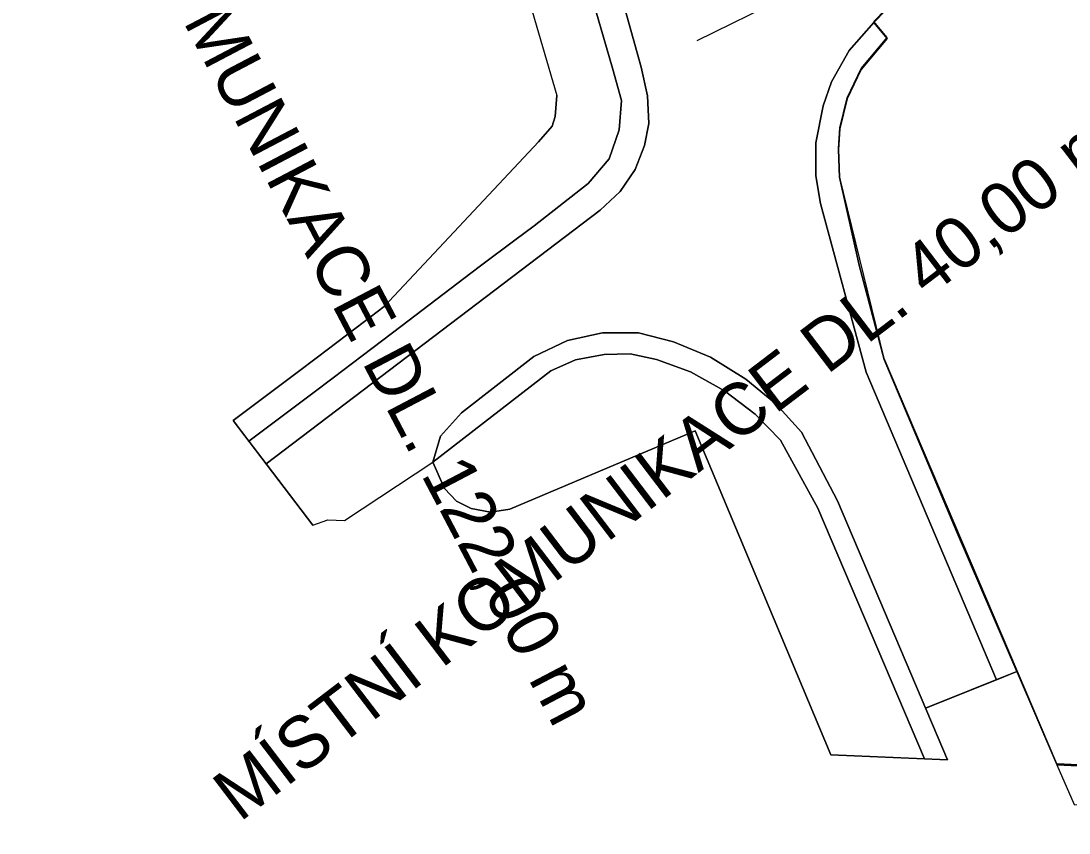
# Model space of a CAD drawing. Extents: x -606444 to -604546, y -1158114 to -1156869.
# Drawn here: x -605208.5 to -605127.5, y -1157433.2 to -1157370.5 of the extents above; entities that cross this region are included whole.
import ezdxf

# ---------------------------------------------------------------- set-up
doc = ezdxf.new("R2010")
doc.units = 0
for name, color, linetype in [('B_CHOD', 7, 'Continuous'), ('B_VOZ', 7, 'Continuous'), ('B_ZELEN', 7, 'Continuous'), ('NS_VB', 7, 'Continuous'), ('NS_VB_POP', 7, 'Continuous'), ('OSAPOP', 7, 'Continuous')]:
    doc.layers.add(name, color=color, linetype=linetype)

msp = doc.modelspace()

# ---------------------------------------------------------------- linework, layer by layer
at = {"layer": 'B_CHOD'}
for p, q in [((-605142.56, -1157370.59), (-605144.46, -1157372.75)), ((-605141.53, -1157371.81), (-605142.56, -1157370.59)), ((-605143.54, -1157374.22), (-605141.53, -1157371.81)), ((-605144.46, -1157372.75), (-605145.82, -1157375.16)), ((-605144.61, -1157376.48), (-605143.54, -1157374.22)), ((-605145.82, -1157375.16), (-605146.48, -1157377.03)), ((-605145.18, -1157378.79), (-605144.61, -1157376.48)), ((-605146.48, -1157377.03), (-605147.04, -1157379.89)), ((-605145.29, -1157380.41), (-605145.18, -1157378.79)), ((-605147.04, -1157379.89), (-605147.04, -1157382.44)), ((-605145.22, -1157382.53), (-605145.29, -1157380.41)), ((-605147.04, -1157382.44), (-605146.67, -1157384.57)), ((-605143.7, -1157389.34), (-605145.22, -1157382.53)), ((-605146.67, -1157384.57), (-605143.14, -1157397.61)), ((-605141.75, -1157396.64), (-605143.7, -1157389.34)), ((-605163.53, -1157394.56), (-605166.24, -1157395.16)), ((-605160.75, -1157394.56), (-605163.53, -1157394.56)), ((-605158.04, -1157395.26), (-605160.75, -1157394.56)), ((-605166.24, -1157395.16), (-605168.83, -1157396.41)), ((-605155.19, -1157396.46), (-605158.04, -1157395.26)), ((-605165.62, -1157396.67), (-605163.39, -1157396.24)), ((-605163.39, -1157396.24), (-605161.39, -1157396.19)), ((-605161.39, -1157396.19), (-605159.35, -1157396.63)), ((-605168.83, -1157396.41), (-605174.42, -1157400.75)), ((-605167.53, -1157397.52), (-605165.62, -1157396.67)), ((-605159.35, -1157396.63), (-605156.73, -1157397.59)), ((-605152.46, -1157398.15), (-605155.19, -1157396.46)), ((-605136.12, -1157410.04), (-605141.75, -1157396.64)), ((-605176.65, -1157404.56), (-605167.53, -1157397.52)), ((-605156.73, -1157397.59), (-605154.1, -1157399.05)), ((-605143.14, -1157397.61), (-605133.089, -1157421.389)), ((-605150.14, -1157400.05), (-605152.46, -1157398.15)), ((-605154.1, -1157399.05), (-605151.74, -1157400.87)), ((-605148.14, -1157402.24), (-605150.14, -1157400.05)), ((-605174.42, -1157400.75), (-605176.05, -1157402.57)), ((-605151.74, -1157400.87), (-605149.78, -1157402.88)), ((-605176.05, -1157402.57), (-605176.65, -1157404.56)), ((-605145.38, -1157407.55), (-605148.14, -1157402.24)), ((-605149.78, -1157402.88), (-605146.89, -1157408.12)), ((-605136.87, -1157427.58), (-605145.38, -1157407.55)), ((-605146.89, -1157408.12), (-605138.655, -1157427.503)), ((-605131.517, -1157420.758), (-605136.12, -1157410.04)), ((-605133.089, -1157421.389), (-605131.517, -1157420.758)), ((-605138.655, -1157427.503), (-605136.87, -1157427.58))]:
    msp.add_line(p, q, dxfattribs=at)
for points in [[(-605164.04, -1157369.69), (-605162.76, -1157374.11), (-605162.07, -1157376.61), (-605162.24, -1157378.89), (-605163.02, -1157381.11), (-605164.65, -1157383.04), (-605168.82, -1157386.29), (-605170.31, -1157387.42), (-605172.85, -1157389.31), (-605173.71, -1157389.95), (-605179.02, -1157394), (-605181.37, -1157395.78), (-605184.35, -1157398.04), (-605185.93, -1157399.23), (-605190.854, -1157402.943), (-605189.528, -1157404.69), (-605163.72, -1157385.1), (-605162.17, -1157383.64), (-605161, -1157381.94), (-605160.28, -1157380.1), (-605159.94, -1157378.4), (-605160.05, -1157376.26), (-605160.55, -1157374.03), (-605161.97, -1157368.95)], [(-605127.071, -1157431.03), (-605075.118, -1157433.238), (-605072.572, -1157430.343), (-605128.42, -1157427.97), (-605127.071, -1157431.03)]]:
    msp.add_lwpolyline(points, dxfattribs=at)
at = {"layer": 'B_VOZ'}
msp.add_lwpolyline([(-605161.97, -1157368.95), (-605160.55, -1157374.03), (-605160.05, -1157376.26), (-605159.94, -1157378.4), (-605160.28, -1157380.1), (-605161, -1157381.94), (-605162.17, -1157383.64), (-605163.72, -1157385.1), (-605189.528, -1157404.69), (-605185.93, -1157409.43), (-605184.77, -1157409.03), (-605183.48, -1157409.07), (-605176.65, -1157404.56), (-605176.05, -1157402.57), (-605174.42, -1157400.75), (-605168.83, -1157396.41), (-605166.24, -1157395.16), (-605163.53, -1157394.56), (-605160.75, -1157394.56), (-605158.04, -1157395.26), (-605155.19, -1157396.46), (-605152.46, -1157398.15), (-605150.14, -1157400.05), (-605148.14, -1157402.24), (-605145.38, -1157407.55), (-605138.564, -1157423.592), (-605133.089, -1157421.389), (-605143.14, -1157397.61), (-605146.67, -1157384.57), (-605147.04, -1157382.44), (-605147.04, -1157379.89), (-605146.48, -1157377.03), (-605145.82, -1157375.16), (-605144.46, -1157372.75), (-605142.56, -1157370.59), (-605135.48, -1157363.22)], dxfattribs=at)
at = {"layer": 'B_ZELEN'}
for p, q in [((-605173.042, -1157355.75), (-605167.056, -1157376.238)), ((-605142.559, -1157370.515), (-605135.479, -1157363.145)), ((-605162.76, -1157374.11), (-605164.04, -1157369.69)), ((-605141.529, -1157371.735), (-605142.559, -1157370.515)), ((-605143.539, -1157374.145), (-605141.529, -1157371.735)), ((-605162.07, -1157376.61), (-605162.76, -1157374.11)), ((-605144.609, -1157376.405), (-605143.539, -1157374.145)), ((-605167.056, -1157376.238), (-605167.177, -1157377.858)), ((-605162.24, -1157378.89), (-605162.07, -1157376.61)), ((-605145.179, -1157378.715), (-605144.609, -1157376.405)), ((-605167.177, -1157377.858), (-605167.433, -1157378.586)), ((-605167.433, -1157378.586), (-605168.47, -1157379.814)), ((-605163.02, -1157381.11), (-605162.24, -1157378.89)), ((-605145.289, -1157380.335), (-605145.179, -1157378.715)), ((-605168.47, -1157379.814), (-605180.407, -1157392.542)), ((-605145.219, -1157382.455), (-605145.289, -1157380.335)), ((-605164.65, -1157383.04), (-605163.02, -1157381.11)), ((-605141.749, -1157396.565), (-605145.219, -1157382.455)), ((-605168.82, -1157386.29), (-605164.65, -1157383.04)), ((-605170.31, -1157387.42), (-605168.82, -1157386.29)), ((-605172.85, -1157389.31), (-605170.31, -1157387.42)), ((-605173.71, -1157389.95), (-605172.85, -1157389.31)), ((-605179.02, -1157394), (-605173.71, -1157389.95)), ((-605180.407, -1157392.542), (-605182.578, -1157394.186)), ((-605182.578, -1157394.186), (-605185.556, -1157396.444)), ((-605181.37, -1157395.78), (-605179.02, -1157394)), ((-605184.35, -1157398.04), (-605181.37, -1157395.78)), ((-605163.39, -1157396.24), (-605165.62, -1157396.67)), ((-605161.39, -1157396.19), (-605163.39, -1157396.24)), ((-605159.35, -1157396.63), (-605161.39, -1157396.19)), ((-605185.556, -1157396.444), (-605187.134, -1157397.633)), ((-605165.62, -1157396.67), (-605167.53, -1157397.52)), ((-605156.73, -1157397.59), (-605159.35, -1157396.63)), ((-605128.419, -1157427.895), (-605141.749, -1157396.565)), ((-605187.134, -1157397.633), (-605192.063, -1157401.35)), ((-605167.53, -1157397.52), (-605176.65, -1157404.56)), ((-605154.1, -1157399.05), (-605156.73, -1157397.59)), ((-605185.93, -1157399.23), (-605184.35, -1157398.04)), ((-605190.854, -1157402.943), (-605185.93, -1157399.23)), ((-605151.74, -1157400.87), (-605154.1, -1157399.05)), ((-605149.78, -1157402.88), (-605151.74, -1157400.87)), ((-605192.063, -1157401.35), (-605190.854, -1157402.943)), ((-605170.69, -1157408.21), (-605156.36, -1157402.16)), ((-605156.36, -1157402.16), (-605145.87, -1157427.19)), ((-605146.89, -1157408.12), (-605149.78, -1157402.88)), ((-605176.65, -1157404.56), (-605175.75, -1157406.6)), ((-605175.75, -1157406.6), (-605174.81, -1157407.58)), ((-605174.81, -1157407.58), (-605173.69, -1157408.14)), ((-605173.69, -1157408.14), (-605172.18, -1157408.43)), ((-605172.18, -1157408.43), (-605170.69, -1157408.21)), ((-605138.655, -1157427.503), (-605146.89, -1157408.12)), ((-605145.87, -1157427.19), (-605138.655, -1157427.503)), ((-605072.571, -1157430.268), (-605128.419, -1157427.895))]:
    msp.add_line(p, q, dxfattribs=at)
at = {"layer": 'NS_VB'}
for p, q in [((-605173.042, -1157355.75), (-605167.056, -1157376.238)), ((-605135.48, -1157363.22), (-605142.56, -1157370.59)), ((-605161.97, -1157368.95), (-605160.55, -1157374.03)), ((-605162.76, -1157374.11), (-605164.04, -1157369.69)), ((-605142.56, -1157370.59), (-605144.46, -1157372.75)), ((-605142.56, -1157370.59), (-605141.53, -1157371.81)), ((-605141.53, -1157371.81), (-605143.54, -1157374.22)), ((-605144.46, -1157372.75), (-605145.82, -1157375.16)), ((-605162.07, -1157376.61), (-605162.76, -1157374.11)), ((-605160.55, -1157374.03), (-605160.05, -1157376.26)), ((-605143.54, -1157374.22), (-605144.61, -1157376.48)), ((-605145.82, -1157375.16), (-605146.48, -1157377.03)), ((-605167.177, -1157377.858), (-605167.056, -1157376.238)), ((-605162.24, -1157378.89), (-605162.07, -1157376.61)), ((-605160.05, -1157376.26), (-605159.94, -1157378.4)), ((-605144.61, -1157376.48), (-605145.18, -1157378.79)), ((-605146.48, -1157377.03), (-605147.04, -1157379.89)), ((-605167.433, -1157378.586), (-605167.177, -1157377.858)), ((-605159.94, -1157378.4), (-605160.28, -1157380.1)), ((-605168.47, -1157379.814), (-605167.433, -1157378.586)), ((-605163.02, -1157381.11), (-605162.24, -1157378.89)), ((-605145.18, -1157378.79), (-605145.29, -1157380.41)), ((-605180.407, -1157392.542), (-605168.47, -1157379.814)), ((-605160.28, -1157380.1), (-605161, -1157381.94)), ((-605147.04, -1157379.89), (-605147.04, -1157382.44)), ((-605145.29, -1157380.41), (-605145.22, -1157382.53)), ((-605164.65, -1157383.04), (-605163.02, -1157381.11)), ((-605161, -1157381.94), (-605162.17, -1157383.64)), ((-605147.04, -1157382.44), (-605146.67, -1157384.57)), ((-605145.22, -1157382.53), (-605143.7, -1157389.34)), ((-605168.82, -1157386.29), (-605164.65, -1157383.04)), ((-605162.17, -1157383.64), (-605163.72, -1157385.1)), ((-605146.67, -1157384.57), (-605143.14, -1157397.61)), ((-605163.72, -1157385.1), (-605189.528, -1157404.69)), ((-605170.31, -1157387.42), (-605168.82, -1157386.29)), ((-605172.85, -1157389.31), (-605170.31, -1157387.42)), ((-605173.71, -1157389.95), (-605172.85, -1157389.31)), ((-605143.7, -1157389.34), (-605141.75, -1157396.64)), ((-605179.02, -1157394), (-605173.71, -1157389.95)), ((-605182.578, -1157394.186), (-605180.407, -1157392.542)), ((-605185.556, -1157396.444), (-605182.578, -1157394.186)), ((-605181.37, -1157395.78), (-605179.02, -1157394)), ((-605166.24, -1157395.16), (-605163.53, -1157394.56)), ((-605163.53, -1157394.56), (-605160.75, -1157394.56)), ((-605160.75, -1157394.56), (-605158.04, -1157395.26)), ((-605168.83, -1157396.41), (-605166.24, -1157395.16)), ((-605158.04, -1157395.26), (-605155.19, -1157396.46)), ((-605184.35, -1157398.04), (-605181.37, -1157395.78)), ((-605165.62, -1157396.67), (-605163.39, -1157396.24)), ((-605163.39, -1157396.24), (-605161.39, -1157396.19)), ((-605161.39, -1157396.19), (-605159.35, -1157396.63)), ((-605187.134, -1157397.633), (-605185.556, -1157396.444)), ((-605174.42, -1157400.75), (-605168.83, -1157396.41)), ((-605167.53, -1157397.52), (-605165.62, -1157396.67)), ((-605159.35, -1157396.63), (-605156.73, -1157397.59)), ((-605155.19, -1157396.46), (-605152.46, -1157398.15)), ((-605141.75, -1157396.64), (-605136.12, -1157410.04)), ((-605192.063, -1157401.35), (-605187.134, -1157397.633)), ((-605176.65, -1157404.56), (-605167.53, -1157397.52)), ((-605156.73, -1157397.59), (-605154.1, -1157399.05)), ((-605143.14, -1157397.61), (-605133.089, -1157421.389)), ((-605185.93, -1157399.23), (-605184.35, -1157398.04)), ((-605152.46, -1157398.15), (-605150.14, -1157400.05)), ((-605190.854, -1157402.943), (-605185.93, -1157399.23)), ((-605154.1, -1157399.05), (-605151.74, -1157400.87)), ((-605150.14, -1157400.05), (-605148.14, -1157402.24)), ((-605176.05, -1157402.57), (-605174.42, -1157400.75)), ((-605151.74, -1157400.87), (-605149.78, -1157402.88)), ((-605185.93, -1157409.43), (-605192.063, -1157401.35)), ((-605176.65, -1157404.56), (-605176.05, -1157402.57)), ((-605156.36, -1157402.16), (-605170.69, -1157408.21)), ((-605145.87, -1157427.19), (-605156.36, -1157402.16)), ((-605148.14, -1157402.24), (-605145.38, -1157407.55)), ((-605149.78, -1157402.88), (-605146.89, -1157408.12)), ((-605183.48, -1157409.07), (-605176.65, -1157404.56)), ((-605175.75, -1157406.6), (-605176.65, -1157404.56)), ((-605174.81, -1157407.58), (-605175.75, -1157406.6)), ((-605173.69, -1157408.14), (-605174.81, -1157407.58)), ((-605145.38, -1157407.55), (-605136.87, -1157427.58)), ((-605172.18, -1157408.43), (-605173.69, -1157408.14)), ((-605170.69, -1157408.21), (-605172.18, -1157408.43)), ((-605146.89, -1157408.12), (-605138.655, -1157427.503)), ((-605185.93, -1157409.43), (-605184.77, -1157409.03)), ((-605184.77, -1157409.03), (-605183.48, -1157409.07)), ((-605136.12, -1157410.04), (-605128.42, -1157427.97)), ((-605131.517, -1157420.758), (-605138.564, -1157423.592)), ((-605136.87, -1157427.58), (-605145.87, -1157427.19)), ((-605128.42, -1157427.97), (-605072.572, -1157430.343)), ((-605128.42, -1157427.97), (-605127.071, -1157431.03))]:
    msp.add_line(p, q, dxfattribs=at)
at = {"layer": 'OSAPOP'}
msp.add_line((-605156.216, -1157371.985), (-605147.265, -1157367.527), dxfattribs=at)

# ---------------------------------------------------------------- texts
at = {"layer": 'NS_VB_POP'}
for s, rotation, p in [('MÍSTNÍ KOMUNIKACE DL. 122,00 m', 297.70257, (-605208.681, -1157346.292)), ('MÍSTNÍ KOMUNIKACE DL. 40,00 m', 37.31216, (-605191.573, -1157432.443))]:
    msp.add_text(s, height=4, rotation=rotation, dxfattribs=at).set_placement(p)

doc.saveas('drawing.dxf')
